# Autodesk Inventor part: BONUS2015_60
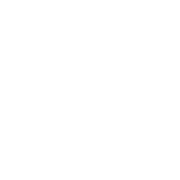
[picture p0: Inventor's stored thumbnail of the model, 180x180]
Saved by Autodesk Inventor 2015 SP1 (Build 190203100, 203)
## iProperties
Created: 2015-05
Part Number: BONUS2015_60
Material: Generisch
Document SubType Name: Modeling
Density: 1 g/cm^3
Appearance: Vorgabe
xx: 60
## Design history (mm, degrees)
